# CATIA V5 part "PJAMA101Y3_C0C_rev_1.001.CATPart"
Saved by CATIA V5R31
Part number: PJAMA101Y3_C0C_rev_1.001
Source: Unknown
Bounding box of the stored display mesh (mm): x 4227.543 to 4268.943, y 385 to 491.463, z 678 to 724.353
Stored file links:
  \\solize.local\damia\dept\DDE_Design\10_order\2305701_JAMA_変換検証STEP3_お手本モデル作成\work\02_マツダ_板金\10_CATIA_V5\231211\PJAMA101Y3_C0C_rev_1.001.CATPart
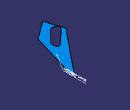
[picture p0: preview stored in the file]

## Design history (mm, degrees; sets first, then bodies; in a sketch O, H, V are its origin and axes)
TTRSSet1
f4a2d38f3ddc11d3a929006094b99c4b_11 "CATTPSSet"
Set1
  DatumSurface1 "OPEN_SHELL #619"
Body1 (main body)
